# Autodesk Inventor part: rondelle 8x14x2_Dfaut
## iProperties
Created: 2006-03
Part Number: rondelle 8x14x2_Dfaut
Document SubType Name: Modeling
Designer: Flavien MARTY
Author: Flavien MARTY
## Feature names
1. Base1
